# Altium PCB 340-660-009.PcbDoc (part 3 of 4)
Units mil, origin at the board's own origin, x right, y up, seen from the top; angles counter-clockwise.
Board outline 2755.91 x 2755.91 mil, 4 copper layers (Top Layer, Int1 (PWR), Int2 (GND), Bottom Layer), stack 53.912 mil thick; 183 components, 253 nets, 930 pads, 492 vias.
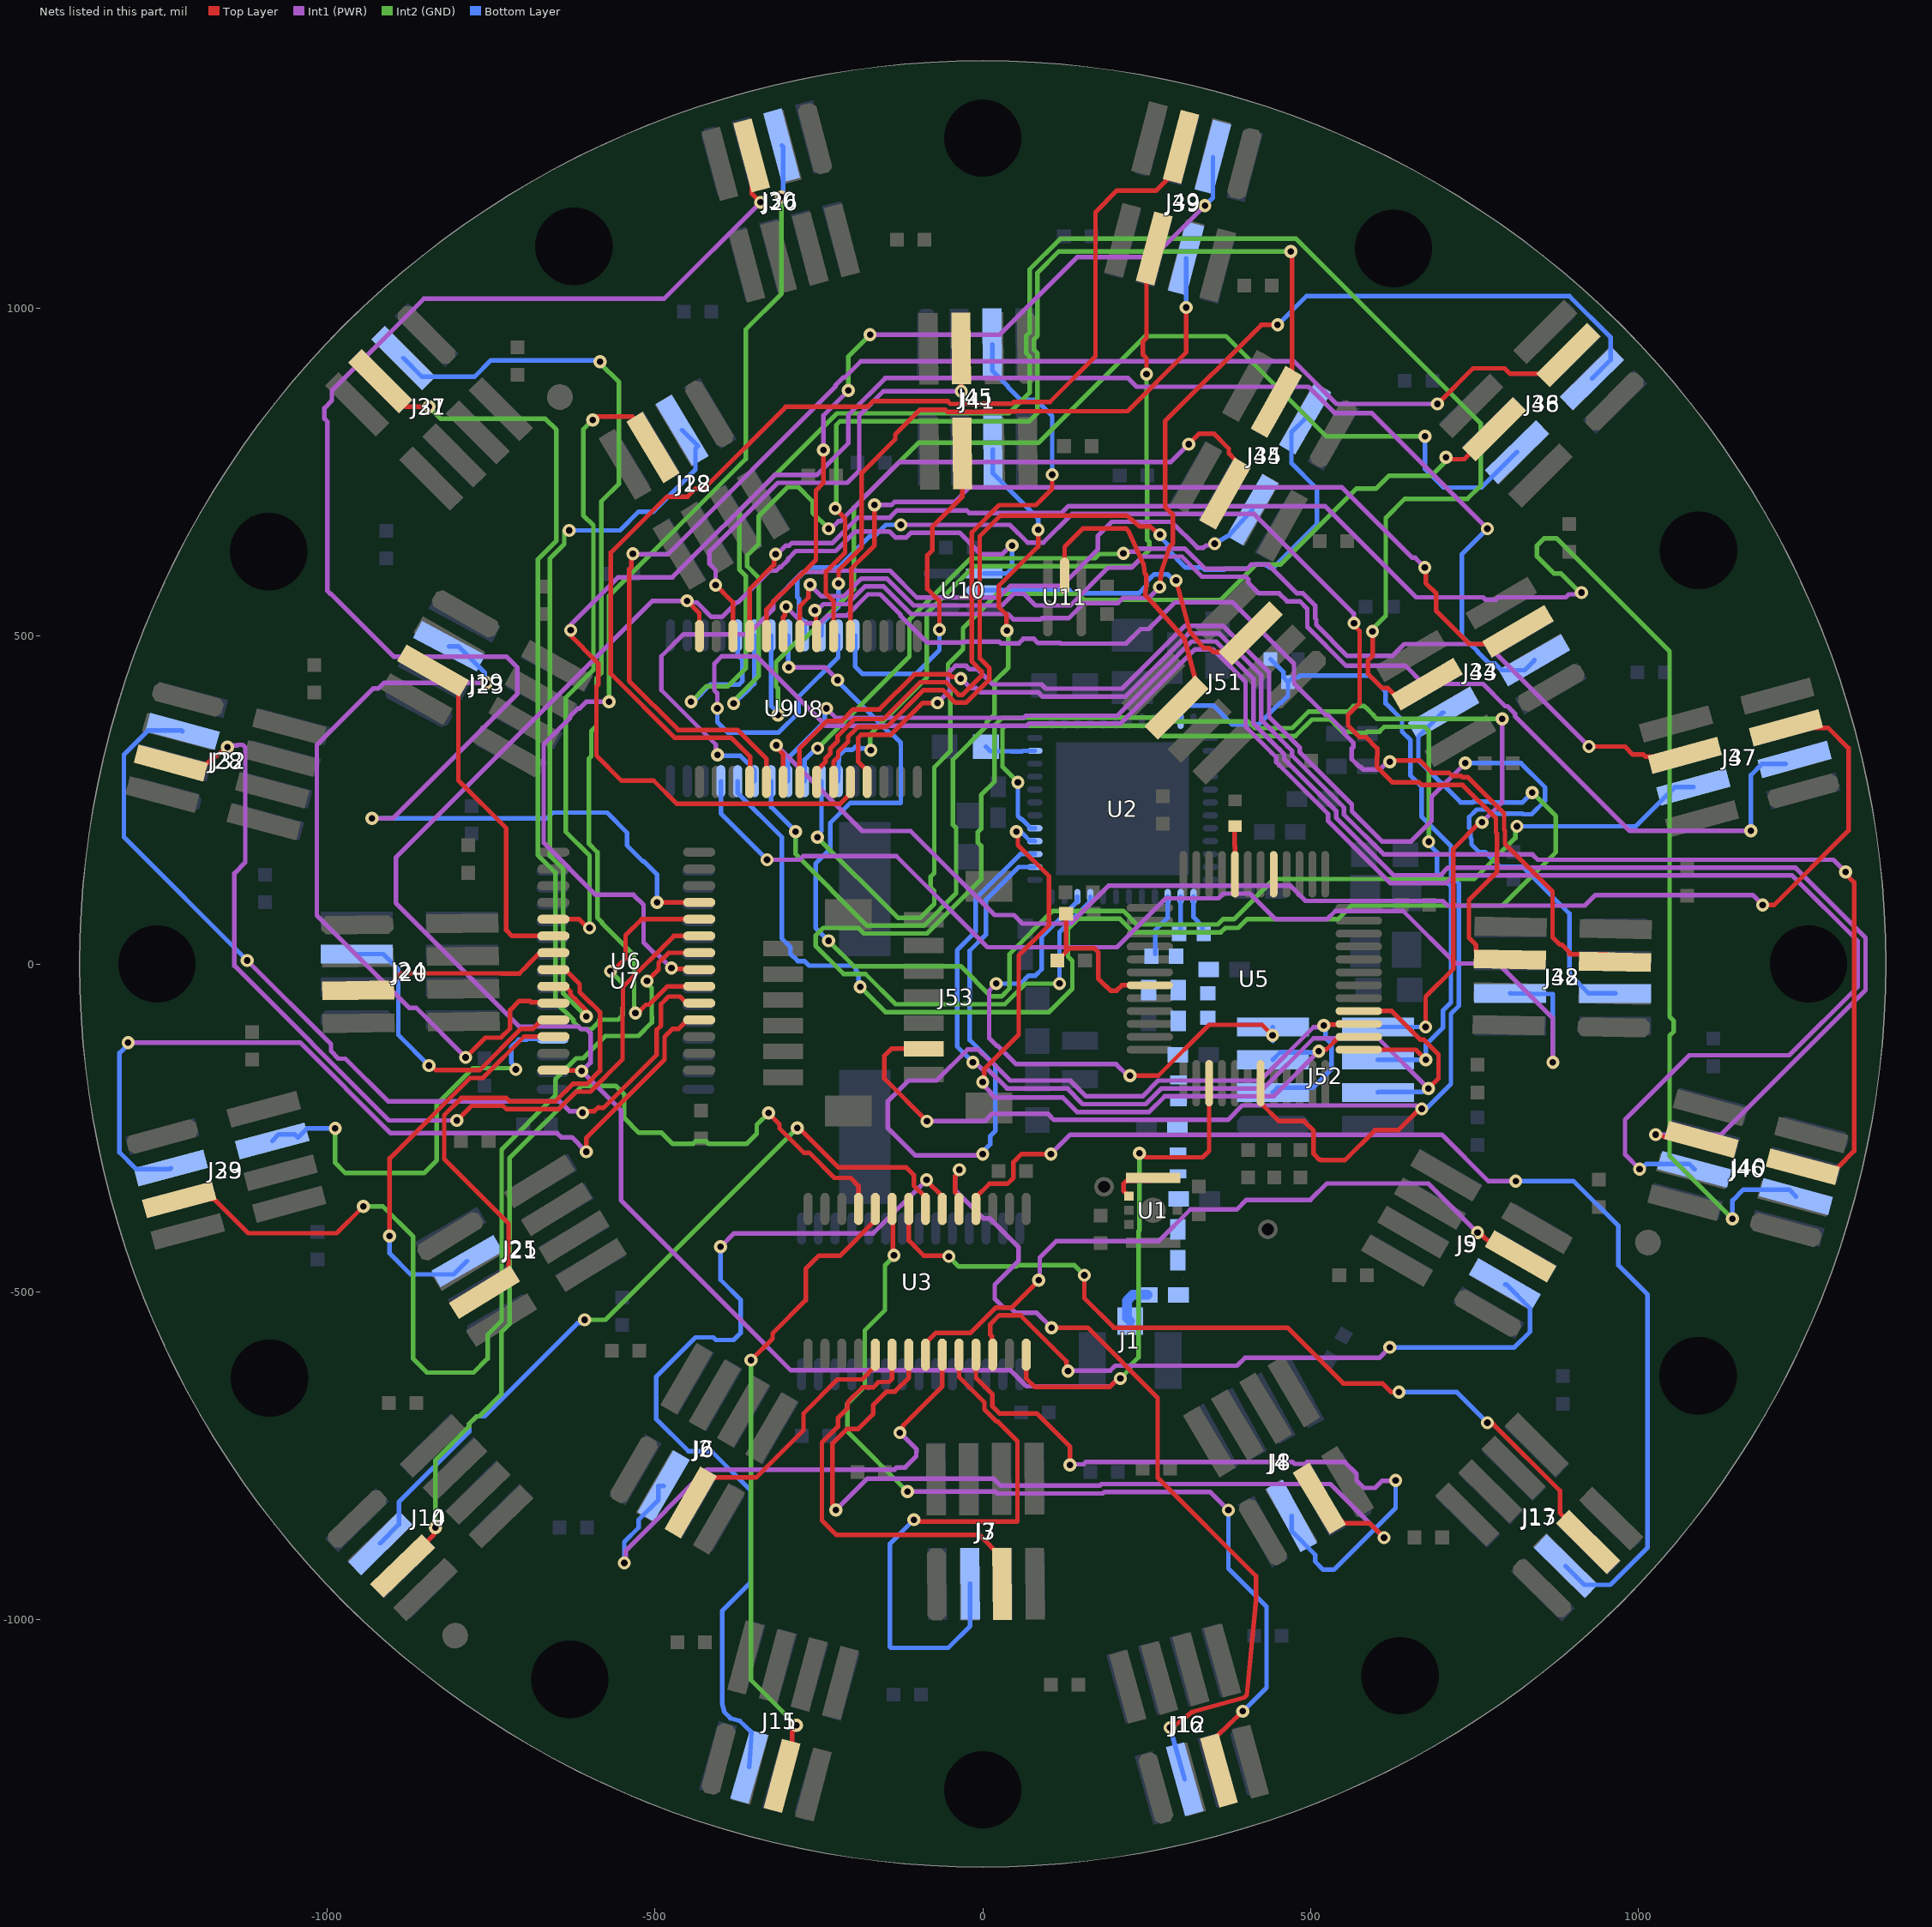
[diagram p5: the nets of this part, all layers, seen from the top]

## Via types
v1: diameter 20, hole 10, Top Layer to Bottom Layer, tented both sides, 489 vias
v2: diameter 20, hole 10, Top Layer to Bottom Layer, 3 vias

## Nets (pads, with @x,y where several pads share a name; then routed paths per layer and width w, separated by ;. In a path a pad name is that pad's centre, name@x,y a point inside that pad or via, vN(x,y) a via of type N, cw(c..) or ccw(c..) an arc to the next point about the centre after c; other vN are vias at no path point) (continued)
MUXA32: J33.6 U7.4 | length 665.4
  Int2 (GND) w7: v1(-988,-251) -988,-303.5 -972.5,-319 -852.37,-319 -833,-299.63 -833,-214.08 -777.92,-159 -714.4,-159 v1(-712.37,-161.02)
  Bottom Layer w7: J33.6@-1084.08,-270.12 -1073.97,-260 -1050,-260 -1045,-265 -1031,-251 v1(-988,-251) ; v1(-712.37,-161.02) -712.37,-157.51 -719.5,-150.38 -719.5,-126.92 -708.08,-115.5 -695.93,-115.5 -695,-114.57 U7.4@-656.22,-114.57
MUXA33: J34.6 U9.19 | length 2667.8
  Top Layer w7: v1(594.61,507.18) 595.2,506.59 595.2,470.1 587.99,462.88 587.99,442.48 609.57,420.9 618.3,420.9 628.2,411 662.8,411 J34.6@678.39,426.59
  Int2 (GND) w7: v1(-445,400) -421.33,423.67 -388.75,423.67 -361.56,450.86 -361.56,592.01 -371.5,601.95 -371.5,690.97 -222.47,840 40,840 71.57,871.57 71.57,926.68 66.27,931.98 66.27,958.07 71.57,963.38 71.57,1059.54 118.53,1106.5 478.08,1106.5 760,824.58 760,730 739.5,709.5 643.92,709.5 615,680.58 615,531.09 594.61,510.7 v1(594.61,507.18)
  Bottom Layer w7: v1(-445,400) -441.5,400 -415.19,426.31 -371.66,426.31 -366.46,431.51 -366.46,463.49 -373.98,471 U9.19@-373.98,501.22
MUXA34: J35.6 U9.20 | length 1354.8
  Top Layer w7: v1(314.2,793) 330.2,809 352.5,809 375.48,786.02 375.48,778.96 385.37,769.06 385.37,733.02 J35.6@369.86,717.51
  Int1 (PWR) w7: v1(-235.05,664.05) -231.53,664.05 -220.08,675.5 -216.92,675.5 -184.6,707.82 -184.6,708.36 -126.97,765.99 287.19,765.99 v1(314.2,793)
  Int2 (GND) w7: v1(-380.1,397.47) -380.1,400.9 -342,439 -342,589.42 -359.5,606.92 -359.5,623.08 -342,640.58 -342,683.08 -297.58,727.5 -281.42,727.5 -259.48,705.56 -259.48,688.48 v1(-235.05,664.05)
  Bottom Layer w7: v1(-380.1,397.47) -379.21,397.47 -362.68,414 -361.89,414 -348.39,427.5 U9.20@-348.39,501.22
MUXA35: J36.6 U9.21 | length 1765.2
  Int2 (GND) w7: v1(-312.53,379.69) -312.53,420.5 -315.4,423.37 -315.4,460.66 -280.02,496.03 -271.98,496.03 -196.5,571.52 -196.5,696.47 -97.97,795 85,795 247.85,957.85 371.23,957.85 524.07,805 v1(675,805)
  Bottom Layer w7: U9.21@-322.8,501.22 -322.8,393.47 -312.53,383.21 v1(-312.53,379.69) ; v1(675,805) 675,755 703.15,726.85 761.03,726.85 J36.6@815.26,781.08
MUXA36: J37.6 U9.22 | length 2229.8
  Int1 (PWR) w7: v1(-295.9,452.58) -240.84,452.58 v1(-221.33,433.08)
  Int2 (GND) w7: v1(-235.37,35.38) -196.58,-3.41 -33.55,-3.41 12.54,-49.5 28.69,-49.5 40.85,-37.34 40.85,15 106.81,80.96 214.36,80.96 235.14,60.18 358.25,60.18 366.27,68.2 383.1,68.2 444.39,129.5 750.08,129.5 812.72,192.14 812.72,207.49 v1(815.21,209.98)
  Bottom Layer w7: U9.22@-297.2,501.22 -296.55,500.57 -296.55,453.24 v1(-295.9,452.58) ; v1(-235.37,35.38) -254.87,54.88 -254.87,153.08 -232.77,175.17 -232.77,214.96 -202.06,245.67 -125,245.67 -125,335 -125.5,335.5 -125.5,338.08 -136.92,349.5 -139.5,349.5 -225,435 -223.25,435 v1(-221.33,433.08) ; v1(815.21,209.98) 996.5,210 1056.16,269.66 J37.6@1084.37,269.66
MUXA37: J38.6 U9.23 | length 1832.4
  Top Layer w7: v1(566.5,520) 566.5,516.48 575,507.98 575,398.03 557.31,380.34 557.31,363.57 574.82,346.06 584.66,346.06 602.16,328.55 602.16,316.97 601.77,316.58 601.77,300.42 625.19,277 665.94,277 669.94,273 732.32,273 783.03,222.29 783.03,200.2 784.88,198.35 784.88,140.5 741.98,97.6 741.98,39.76 752.89,28.85 752.89,18.92 765.15,6.66 J38.6@804.62,6.66
  Int1 (PWR) w7: v1(-125,670) 41.33,670 68.33,643 92.58,643 136.08,686.5 414.32,686.5 566.16,534.65 566.16,520.34 v1(566.5,520)
  Bottom Layer w7: U9.23@-271.61,501.22 -271.61,520.77 -280.5,529.66 -280.5,556.87 -282.99,559.35 -282.99,586.56 -264.55,605 -219.71,605 -172.07,652.64 -164.98,652.64 -147.62,670 v1(-125,670)
MUXA38: J39.6 U9.24 | length 995.1
  Top Layer w7: v1(-220,580.39) -219.82,580.58 -219.82,600.89 -184.6,636.11 -184.6,749.32 -133.5,800.42 -133.5,808.02 -96.15,845.37 -57.34,845.37 -54.35,842.38 -0.06,842.38 0.4,842.84 49.94,842.84 50.39,843.29 220.87,843.29 310.47,932.89 v1(310.47,1001.57)
  Bottom Layer w7: U9.24@-246.02,501.22 -246.02,518.94 -220,544.96 v1(-220,580.39) ; v1(310.47,1001.57) J39.6@310.47,1076.4
MUXA39: J40.6 U9.25 | length 3146.6
  Int1 (PWR) w7: v1(-405,390) -405,413.05 -409.5,417.55 -409.5,458.08 -398.08,469.5 -345.58,469.5 -239.64,363.57 67.57,363.57 70.82,366.82 210.65,366.82 323.83,480 351.21,480 401,430.21 401,362.07 440.82,322.24 448,315.07 448,307.82 527.2,228.61 527.2,218.01 621.71,123.5 708.05,123.5 719.55,135 1235,135 1335,35 1335,-35 1230.59,-139.41 1078.02,-139.41 980,-237.42 980,-290.65 v1(1002.35,-313)
  Bottom Layer w7: v1(-405,390) -405,369 -389.15,353.15 -311.5,353.15 -281,383.65 -281,407.43 -220.43,468 U9.25@-220.43,501.22 ; v1(1002.35,-313) 1004.95,-313 1012.95,-305 1077.79,-305 J40.6@1086.14,-313.35
MUXA40: J41.6 U9.26 | length 525.6
  Top Layer w7: v1(-66,510) -66,553.65 -84.5,572.15 -84.5,623.35 -76.79,631.06 -76.79,667.21 -31.28,712.72 J41.6@-31.28,778.83
  Bottom Layer w7: U9.26@-194.84,501.22 -194.84,453.94 -183.42,442.52 -102.32,442.52 -66,478.84 v1(-66,510)
MUXA41: J42.6 U9.11 | length 1767.1
  Int1 (PWR) w7: v1(-329,159) -279.14,159 -273.64,164.5 -131.82,164.5 7.18,25.5 204.93,25.5 279.43,100 359.74,100 366.94,107.2 407.8,107.2 446.8,68.2 525.48,68.2 538.11,80.84 641.49,80.84 721.7,0.62 786.38,0.62 870,-83 v1(870,-150)
  Bottom Layer w7: U9.11@-399.57,278.78 -399.57,229.57 v1(-329,159) ; J42.6@804.88,-45 870,-46 v1(870,-150)
MUXA42: J43.6 U9.10 | length 2097.7
  Int2 (GND) w7: v1(-187,-34.91) -148.41,-73.5 101.25,-73.5 136.67,-38.08 136.67,4.49 130.14,11.01 130.14,53.58 145.53,68.96 209.39,68.96 223.35,55 230.17,48.18 363.22,48.18 370.04,55 390,55 403.2,68.2 541.99,68.2 562.78,88.99 793.07,88.99 874.5,170.42 874.5,225.53 v1(838.56,261.48)
  Bottom Layer w7: U9.10@-373.98,278.78 -373.98,261.06 -306.5,193.59 -306.5,38.92 -293.56,25.98 -293.56,15.74 -282.13,4.32 -271.9,4.32 -264.96,-2.61 -198.1,-2.61 -193.15,-7.56 -193.15,-10.7 -189.44,-14.41 -189.44,-32.47 v1(-187,-34.91) ; J43.6@703.12,383.29 701.35,383.29 664.77,346.71 664.77,310.96 729.23,246.5 747.67,246.5 748.68,247.51 774.78,247.51 775.79,246.5 823.58,246.5 v1(838.56,261.48)
MUXA43: J44.6 U9.9 | length 1348.7
  Int1 (PWR) w7: v1(-404.75,318.79) -407.24,321.28 -407.24,334.66 -490.31,417.73 -490.31,469.37 -456.73,502.95 -358.05,502.95 -319.5,541.5 -319.5,553.08 -274.59,597.99 -244.51,597.99 -242.61,599.89 -141.4,599.89 -100.51,559 24.45,559 41.95,576.5 120.08,576.5 175.5,631.92 175.5,653.08 196.92,674.5 288.08,674.5 327.58,635 337,635 340.57,638.57 351.51,638.57 v1(354,641.06)
  Bottom Layer w7: v1(-404.75,318.79) -403.47,317.51 -369.9,317.51 -348.39,296 U9.9@-348.39,278.78 ; v1(354,641.06) 376.3,654.12 J44.6@411.59,693.12
MUXA44: J45.6 U9.8 | length 1210.8
  Top Layer w7: v1(37.05,508.68) 36.32,509.42 36.32,532.68 24.5,544.5 24.5,576.92 84.5,636.92 v1(84.5,662.5)
  Int2 (GND) w7: v1(-285.5,202) -285.5,167.55 -176.45,58.5 -89.88,58.5 -40.5,107.88 -40.5,207.42 -45.26,212.18 -45.26,311.71 6,362.97 6,368.84 18,380.84 18,431.23 39,452.23 39,506.74 v1(37.05,508.68)
  Bottom Layer w7: U9.8@-322.8,278.78 -322.8,239.3 v1(-285.5,202) ; J45.6@15.5,785.04 15.5,748.5 84.5,679.5 v1(84.5,662.5)
MUXA45: J46.6 U9.7 | length 2584.1
  Top Layer w7: v1(1026.93,-260.41) 1044.12,-265.03 J46.6@1096.59,-267.89
  Int1 (PWR) w7: v1(-238.5,390) -224.07,375.57 62.6,375.57 65.85,378.82 205.68,378.82 318.86,492 356.18,492 413,435.18 413,367.04 452.82,327.21 460,320.04 460,312.79 539.2,233.58 539.2,222.98 626.68,135.5 698.58,135.5 710,146.92 714.5,146.92 714.58,147 1226.92,147 1239.97,147 1347,39.97 1347,26.92 1347,-39.97 1340.56,-46.42 1126.56,-260.41 v1(1026.93,-260.41)
  Bottom Layer w7: U9.7@-297.2,278.78 -297.2,313.89 -240.99,370.1 -240.99,387.51 v1(-238.5,390)
MUXA46: J47.6 U9.6 | length 1710.5
  Top Layer w7: v1(925.06,331.61) 979.81,331.61 991.92,319.5 1008.08,319.5 1011.36,316.21 1069.29,316.21 J47.6@1071.13,318.05
  Int1 (PWR) w7: v1(214.5,626.52) 216.99,629.01 234.46,629.01 239.01,633.56 308.88,633.56 339.6,602.84 403.31,602.84 409.74,609.26 435.89,609.26 479.8,565.36 488.74,565.36 507.19,546.91 507.19,527.47 509,525.66 509,517.3 556.3,470 624.98,470 643.01,488.03 768.65,488.03 v1(925.06,331.61)
  Int2 (GND) w7: v1(-251.89,329.11) -111.78,469.22 -111.78,525.19 -18.05,618.92 171.5,618.92 178.08,625.5 213.48,625.5 v1(214.5,626.52)
  Bottom Layer w7: U9.6@-271.61,278.78 -271.61,311.61 -254.11,329.11 v1(-251.89,329.11)
MUXA47: J48.6 U9.5 | length 1724.7
  Top Layer w7: v1(706.89,773.11) 710,770 734.66,770 J48.6@780.33,815.67
  Int2 (GND) w7: v1(-252.27,193.27) -129.5,70.5 -115.09,70.5 -94.85,70.5 -74,91.35 -74,111.42 -79.5,116.92 -79.5,133.08 -74,138.58 -74,299.94 -49.5,324.44 -49.5,423.89 -52.97,427.36 -52.97,457.03 -30,480 -30,512.25 22.25,564.5 145.67,564.5 154.67,555.5 362.92,555.5 416.69,609.26 454.26,609.26 570,725 600,725 620,745 685,745 710,770 v1(706.89,773.11)
  Bottom Layer w7: v1(-252.27,193.27) -252.27,196.79 -246.02,203.04 U9.5@-246.02,278.78
MUXA48: J49.6 U9.4 | length 1191.3
  Top Layer w7: v1(250,900) 250,923.9 244.46,929.43 244.46,949.81 250,955.35 250,1079.83 J49.6@261.82,1091.65
  Int2 (GND) w7: v1(-170.72,326.17) -171.76,327.21 -171.76,350.24 -85.5,436.5 -85.5,534.5 -13.08,606.92 229.35,606.92 254.35,631.92 254.35,643.58 251,646.92 251,760.45 250,761.45 v1(250,900)
  Bottom Layer w7: U9.4@-220.43,278.78 -219.43,318 -210.82,326.61 -198.9,326.61 -194.24,331.28 -188.44,331.28 -185.82,328.66 -173.2,328.66 v1(-170.72,326.17)
MUXA49: J51.6 U11.2 | length 464
  Top Layer w7: U11.2@125,592.29 125,636.58 152.92,664.5 217.12,664.5 218.43,664.5 222.53,660.4 245.73,608.23 247.31,595.27 249.5,593.08 249.5,576.92 248.38,567.53 248.38,561.73 259.35,550.76 307.87,496.25 324.2,435.21 J51.6@295.67,391.03
MUXB1: J2.5 U3.19 | length 401.4
  Top Layer w7: J2.5@-445.67,-821.73 -445.67,-820.08 -409.04,-783.45 -345.52,-783.45 -273.49,-711.43 -273.49,-685.92 -221.58,-634 -184.04,-634 -163.98,-613.94 U3.19@-163.98,-596.22
MUXB2: J3.5 U3.20 | length 654.3
  Top Layer w7: U3.20@-138.39,-596.22 -138.39,-633.24 -142.28,-637.13 -159.39,-638.39 -167,-646 -183.46,-646 -205.5,-668.04 -205.5,-669.84 -206.35,-670.69 -206.35,-677.92 -221,-692.57 -221,-706.03 -245.35,-730.38 -245.35,-849.15 -223.5,-871 -5.38,-871 29.62,-906 J3.5@29.62,-946.12
MUXB3: J4.5 U3.21 | length 1323.6
  Top Layer w7: v1(-224,-833) -224,-829.48 -229.5,-823.98 -229.5,-731.92 -206.96,-709.38 -189.89,-709.38 -167.35,-686.84 -167.35,-673.42 -146.3,-652.37 -133.84,-652.37 -112.8,-631.33 U3.21@-112.8,-596.22 ; J4.5@513.61,-815.67 513.61,-816.17 550.7,-853.26 590.26,-853.26 v1(612.29,-875.29)
  Int1 (PWR) w7: v1(-224,-833) -176.5,-785.5 16.98,-785.5 27.48,-796 178.49,-796 180.99,-793.5 530.5,-793.5 v1(612.29,-875.29)
MUXB4: J5.5 U3.22 | length 1054.8
  Top Layer w7: U3.22@-87.2,-596.22 -87.2,-578.5 -71.81,-563.11 -18.82,-563.11 20.15,-524.14 44.38,-524.14 85.27,-483.25 v1(85.27,-482.45) ; v1(755,-410) 758.52,-410 778.52,-430 J5.5@790,-430
  Int1 (PWR) w7: v1(85.27,-482.45) 86.97,-480.75 86.97,-448.03 111.97,-423.03 268.48,-423.03 317.01,-374.5 387.76,-374.5 402.26,-360 500,-360 525,-335 680,-335 v1(755,-410)
MUXB5: J6.5 U3.23 | length 862
  Top Layer w7: v1(-126.38,-715.17) -126.38,-711.65 -121.96,-707.24 -121.96,-704.59 -61.61,-644.25 U3.23@-61.61,-596.22
  Int1 (PWR) w7: v1(-547,-914) -544.51,-911.51 -544.51,-894.96 -421.05,-771.5 -134.54,-771.5 -131.26,-768.22 -118.22,-768.22 -101.32,-751.32 -101,-740.5 v1@-126.33,-715.17
  Bottom Layer w7: v1(-547,-914) -547,-882 -525,-860 -525,-847.98 -494.69,-817.68 -494.69,-796.69 J6.5@-486.88,-796.69
MUXB6: J7.5 U3.24 | length 861.8
  Top Layer w7: v1(-105,-848) -102,-851 52,-851 53,-850 53,-727.94 23.15,-698.08 21.02,-698.08 2.56,-679.63 2.56,-668.91 -36.02,-630.32 U3.24@-36.02,-596.22
  Bottom Layer w7: v1(-105,-848) -141.5,-884.5 -141.5,-1042 -140,-1043.5 -52.66,-1043.5 -19.16,-1010 J7.5@-19.16,-945.76
MUXB7: J8.5 U3.25 | length 1082.6
  Top Layer w7: U3.25@-10.43,-596.22 -10.43,-631.33 14.56,-656.32 14.56,-674.66 25.99,-686.08 83.08,-686.08 133,-736 v1(133,-764.5)
  Int1 (PWR) w7: v1(133,-764.5) 134,-763.5 153.5,-763.5 157,-760 473.08,-760 475.91,-762.83 492.06,-762.83 494.9,-760 552.45,-760 570.5,-778.05 570.5,-788.08 581.92,-799.5 598.45,-799.5 609.5,-788.45 629.55,-788.45 v1(630,-788)
  Bottom Layer w7: J8.5@471.44,-842.3 471.44,-865.61 507.37,-901.54 507.37,-911.98 519.62,-924.23 535.77,-924.23 630,-830 v1(630,-788)
MUXB8: J9.5 U3.26 | length 1033.8
  Top Layer w7: U3.26@15.16,-596.22 13.86,-594.92 13.86,-568.11 11.58,-565.83 11.58,-549.68 25.12,-536.14 57.74,-536.14 127.77,-606.18 127.77,-618.69 v1(130.26,-621.17)
  Int1 (PWR) w7: v1(130.26,-621.17) 130.94,-620.5 194.42,-620.5 201.92,-613 388.05,-613 400.05,-601 605,-601 v1(621,-585)
  Bottom Layer w7: v1(621,-585) 811.31,-585 835.1,-561.21 835.1,-525.45 798.53,-488.88 J9.5@796.76,-488.88
MUXB9: J10.5 U3.11 | length 1443.8
  Top Layer w7: J10.5@-885.18,-918.69 -837.49,-871 -837.49,-862.49 v1(-835,-860) ; v1(-326.65,-227.35) -326.65,-228.02 -310.01,-244.65 -310.01,-250.86 -272.72,-288.15 -264.57,-288.15 -226.22,-326.5 -201.74,-326.5 -189.57,-338.67 U3.11@-189.57,-373.78
  Int2 (GND) w7: v1(-835,-860) -835,-757 -783.44,-705.44 -783.44,-701.55 -772.02,-690.13 -768.13,-690.13 -734.5,-656.5 -734.5,-561.92 -722,-549.42 -722,-296.58 -611.42,-186 -560,-186 -547,-199 -547,-235 -524.5,-257.5 -490.08,-257.5 -473.08,-274.5 -442.08,-274.5 -438.08,-270.5 -421.92,-270.5 -417.92,-274.5 -360.5,-274.5 -344.82,-258.82 -344.82,-245.52 v1(-326.65,-227.35)
MUXB10: J11.5 U3.10 | length 1000.6
  Top Layer w7: v1(-353.59,-604.58) -320.63,-571.62 -320.63,-563.66 -270.07,-513.1 -270.07,-465.07 -250,-445 -217.48,-445 -163.98,-391.5 U3.10@-163.98,-373.78 ; J11.5@-306.44,-1238.85 -290.62,-1223.03 -290.62,-1171.53 -284.27,-1165.19 v1(-284.27,-1161.67)
  Int2 (GND) w7: v1(-353.59,-604.58) -353.59,-1092.35 v1(-284.27,-1161.67)
MUXB11: J12.5 U3.9 | length 1456.4
  Top Layer w7: U3.9@-138.39,-373.78 -137.09,-375.08 -137.09,-442.87 v1(-135.43,-444.54) ; J12.5@360.5,-1230.52 357.42,-1178.01 375.54,-1160.54 v1(396.89,-1140.2)
  Int1 (PWR) w7: v1(-115,-805) 19.51,-805 22.51,-808 183.46,-808 185.96,-805.5 346.9,-805.5 v1(374.79,-833.39)
  Int2 (GND) w7: v1(-135.43,-444.54) -135.43,-446.11 -149.13,-459.82 -149.13,-528.3 -179.89,-559.05 -179.89,-644.23 -206.35,-670.69 -206.35,-713.65 v1(-115,-805)
  Bottom Layer w7: v1(374.79,-833.39) 374.79,-922.21 433,-980.42 433,-1104.08 v1(396.89,-1140.2)
MUXB12: J13.5 U3.8 | length 1317.8
  Top Layer w7: U3.8@-112.8,-373.78 -112.8,-422.2 -90,-445 -52.98,-445 v1(-51.67,-446.31) ; v1(155,-475) 155,-510 200,-555 465,-555 550,-640 610,-640 623.39,-653.39 v1(635.15,-653.39) ; v1(770,-700) 772.49,-702.49 779.46,-702.49 880.88,-803.91 880.88,-837.79 923.67,-880.58 J13.5@923.67,-881.78
  Int2 (GND) w7: v1(-51.67,-446.31) -36.38,-461.61 50.78,-461.61 52.62,-459.77 139.77,-459.77 v1(155,-475)
  Bottom Layer w7: v1(635.15,-653.39) 723.39,-653.39 v1(770,-700)
MUXB13: J14.5 U3.7 | length 1192.8
  Top Layer w7: v1(-283,-250.3) -280.23,-250.3 -220.03,-310.5 -116.55,-310.5 -105.13,-321.92 -105.13,-338.14 -87.2,-356.06 U3.7@-87.2,-373.78
  Int2 (GND) w7: v1(-607.5,-543) -575.7,-543 v1(-283,-250.3)
  Bottom Layer w7: J14.5@-919.41,-883.81 -890.94,-855.34 -890.94,-820.99 -783.44,-713.49 -783.44,-701.55 -772.02,-690.13 -760.08,-690.13 -617.72,-547.77 -615.79,-547.77 -611.02,-543 v1(-607.5,-543)
MUXB14: J15.5 U3.6 | length 1431
  Top Layer w7: v1(-85.63,-329.5) -85.63,-330.77 -61.61,-354.79 U3.6@-61.61,-373.78
  Int1 (PWR) w7: v1(-400.03,-431.55) -379.48,-411 -167.13,-411 v1(-85.63,-329.5)
  Bottom Layer w7: v1(-400.03,-431.55) -400.03,-481.81 -369.5,-512.34 -369.5,-563.18 -380,-573.68 -407.06,-573.68 -411.01,-569.74 -438.07,-569.74 -498.27,-629.93 -498.27,-694.31 -449.08,-743.5 -413.81,-743.5 -354.41,-802.9 -354.41,-943.78 -397.67,-987.05 -397.67,-1125.03 -397.67,-1127.93 -394.2,-1141.63 -384.92,-1150.91 -370.58,-1155.02 -352.57,-1172.66 J15.5@-356.09,-1225.14
MUXB15: J16.5 U3.5 | length 1364.7
  Top Layer w7: U3.5@-36.02,-373.78 -36.02,-354.23 -42.24,-348.01 -42.24,-324.37 -35.5,-317.63 v1(-35.5,-314.11) ; v1(105,-555) 160.08,-555 267,-661.92 267,-784.02 417.07,-934.09 417.07,-970.3 403.08,-1115.3 399,-1119.38 320.69,-1141.09 319.34,-1141.47 289.07,-1165.21 286.65,-1165.21 286.23,-1165.21 v1(285.89,-1165.17)
  Int1 (PWR) w7: v1(-35.5,-314.11) -35.5,-317.63 -42.24,-324.37 -42.24,-344.84 1.3,-388.38 10.96,-388.38 54.5,-431.92 54.5,-453.47 18.39,-489.58 18.39,-511.13 31.41,-524.14 42.02,-524.14 49.88,-532 82,-532 v1(105,-555)
  Bottom Layer w7: v1(285.89,-1165.17) 294,-1194.44 J16.5@308.13,-1243.88
MUXB16: J17.5 U3.4 | length 1778.7
  Top Layer w7: U3.4@-10.43,-373.78 -10.43,-356.06 10.36,-335.27 38.02,-335.27 47,-326.29 47,-302.25 59.25,-290 v1(103.93,-290)
  Int1 (PWR) w7: v1(103.93,-290) 133.43,-260.5 700.5,-260.5 771.39,-331.39 v1(813.3,-331.39)
  Bottom Layer w7: v1(813.3,-331.39) 901.39,-331.39 970,-400 970,-460 1014.57,-504.57 1014.57,-890.43 957.72,-947.28 917.9,-947.28 J17.5@889.61,-918.99
MUXB17: J18.5 U6.19 | length 973.7
  Top Layer w7: U6.19@-655,68.23 -615.76,68.23 -602.54,55 v1(-600,55) ; v1(-595,830) -592.52,830 -597.52,835 -535,835 J18.5@-520,820
  Int2 (GND) w7: v1(-600,55) -600,165.5 -636.21,201.71 -636.21,406.33 -594,448.54 -594,669.01 -609.5,684.51 -609.5,815.5 v1(-595,830)
MUXB18: J19.5 U6.20 | length 488.6
  Top Layer w7: J19.5@-810,430 -800.19,420.19 -800.19,280.26 -727,207.08 -727,51.42 -718.22,42.64 U6.20@-655,42.64
MUXB19: J20.5 U6.21 | length 322
  Top Layer w7: J20.5@-952.79,-40.45 -912.99,-40.45 -886.96,-14.42 -734.33,-14.42 -734.25,-14.5 -706.92,-14.5 -695.05,-2.63 -695.05,-2 -676,17.05 U6.21@-655,17.05
MUXB20: J21.5 U6.22 | length 790.8
  Top Layer w7: J21.5@-760.18,-500.77 -723.54,-464.13 -723.54,-395.96 -821.79,-297.71 -821.79,-230.64 -795.65,-204.5 -726.95,-204.5 -721.95,-209.5 -651.89,-209.5 -625.3,-182.92 -603.84,-182.92 -584,-163.08 -584,-73.79 -587.84,-69.95 -587.84,-69.59 -598.42,-59 -599.31,-59 -609.89,-48.42 -614.91,-43.36 -614.91,-30.91 -637.28,-8.54 U6.22@-655,-8.54
MUXB21: J22.5 U6.23 | length 1161.1
  Top Layer w7: U6.23@-655,-34.13 -636.67,-34.13 -629,-41.81 -629,-46.24 -621.89,-53.35 -621.89,-53.86 -605,-70.75 v1(-605,-80)
  Int2 (GND) w7: v1(-631,661.46) -638.5,661.46 -638.5,640.53 -660.21,618.82 -660.21,164.68 -640,144.47 -640,-45 v1(-605,-80)
  Bottom Layer w7: v1(-631,661.46) -553.54,661.46 -525,690 -502.64,690 -438.36,754.29 -438.36,786.3 -434.5,790.15 J22.5@-458.8,814.45
MUXB22: J23.5 U6.24 | length 1150.1
  Top Layer w7: v1(-789.04,-142.54) -759,-112.5 -735.19,-112.5 -721.13,-98.44 -721.13,-70.56 -707.08,-56.5 -690.92,-56.5 -689,-58.43 -656.3,-58.43 U6.24@-655,-59.72
  Int1 (PWR) w7: v1(-789.04,-142.54) -864.58,-67 -875.08,-67 -1016.07,73.99 -1016.07,334.27 -929.88,420.46 -921.92,420.46 -913.38,429 v1(-757,429)
  Bottom Layer w7: J23.5@-814.02,484.68 -800.11,484.68 -759.49,444.06 -759.49,431.49 v1(-757,429)
MUXB23: J24.5 U6.25 | length 463.9
  Top Layer w7: v1(-845,-155) -841.48,-155 -834.44,-162.04 -767.76,-162.04 -704.63,-98.91 -686.31,-98.91 -672.72,-85.31 U6.25@-655,-85.31
  Bottom Layer w7: J24.5@-955.12,15 -914.76,15 -891.7,-8.07 -891.7,-108.3 v1(-845,-155)
MUXB24: J25.5 U6.26 | length 611.5
  Top Layer w7: v1(-905,-415) -905,-296.88 -782.16,-174.04 -762.79,-174.04 -699.66,-110.91 U6.26@-655,-110.91
  Bottom Layer w7: v1(-905,-415) -905,-441.68 -873.09,-473.59 -807.06,-473.59 J25.5@-786.88,-453.41
MUXB25: J26.5 U6.11 | length 2437.8
  Top Layer w7: v1(-497,93.82) U6.11@-432.56,93.82 ; J26.5@-352.59,1233.43 -352.59,1175.59 v1(-339,1162)
  Int1 (PWR) w7: v1(-932,222) -900,222 -710,412 -710,452 -726.83,468.83 -898.83,468.83 -995,565 -995.9,565 -1000,569.1 -1000,827.42 -1004.5,831.92 -1004.5,848.08 -993.08,859.5 -993.08,874.5 -852.58,1015 -486,1015 v1(-339,1162)
  Bottom Layer w7: v1(-932,222) -664.91,222 -656.07,230.84 -573.27,230.84 -542.7,200.27 -542.7,180.73 -518.47,156.5 -516.95,156.5 -497,136.55 v1(-497,93.82)
MUXB26: J27.5 U6.10 | length 1591.9
  Top Layer w7: J27.5@-919.28,889.07 -880.21,850 v1(-845,850) ; v1(-568,-11) -564.5,-11 -545,8.5 -545,43.64 -520.41,68.23 U6.10@-432.56,68.23
  Int2 (GND) w7: v1(-845,850) -826.74,831.74 -667.24,831.74 -650.5,815 -650.5,645.5 -678.85,617.15 -678.85,166.35 -652,139.5 -652,-58 -625,-85 -624.5,-85 -624.5,-88.08 -613.08,-99.5 -596.92,-99.5 -585.5,-88.08 -585.5,-85 -556,-85 -549.5,-78.5 -549.5,-66.92 -548.84,-66.26 -548.84,-30.16 v1(-568,-11)
MUXB27: J28.5 U6.9 | length 1458
  Top Layer w7: J28.5@-1238.86,306.55 -1186.32,303.96 v1(-1152.38,330.64) ; v1(-802.29,-238.71) -780.08,-216.5 -731.92,-216.5 -726.92,-221.5 -646.92,-221.5 -620.33,-194.92 -598.87,-194.92 -549.5,-145.55 -549.5,-66.92 -548.84,-66.26 -548.84,-34.98 -471.21,42.64 U6.9@-432.56,42.64
  Int1 (PWR) w7: v1(-1152.38,330.64) -1149.89,333.12 -1137.51,333.12 -1136.32,334.32 -1129.32,334.32 -1125.22,330.22 -1125.22,154.78 -1141.79,138.21 -1141.79,-2.79 -905.86,-238.71 v1(-802.29,-238.71)
MUXB28: J29.5 U6.8 | length 1554.5
  Top Layer w7: J29.5@-1225.91,-359.89 -1224.65,-358.63 -1172.93,-358.63 -1120.66,-410.9 -985.9,-410.9 v1(-945,-370) ; v1(-512.3,-26.03) -494.5,-8.22 -494.5,1.7 -479.15,17.05 U6.8@-432.56,17.05
  Int2 (GND) w7: v1(-945,-370) -915.19,-370 -869,-416.19 -869,-602.58 -848.08,-623.5 -776.92,-623.5 -755.46,-602.04 -755.46,-565.91 -734,-544.45 -734,-283 -652,-201 -652,-175.92 -619.99,-143.92 -609.76,-143.92 -575.85,-110 -525.49,-110 -504.82,-89.33 -504.82,-80.18 -505,-80 -505,-36.72 -512.3,-29.41 v1(-512.3,-26.03)
MUXB29: J30.5 U6.7 | length 1589.5
  Top Layer w7: v1(-475,-6.37) -473.92,-7.46 -433.64,-7.46 U6.7@-432.56,-8.54
  Int1 (PWR) w7: v1(-570,400) -605,400 -615.5,389.5 -618.08,389.5 -629.5,378.08 -629.5,375.5 -670,335 -670,185 -590.5,105.5 -532.92,105.5 -517.46,90.03 -517.46,32.46 -499.28,14.28 -495.66,14.28 v1(-475,-6.37)
  Int2 (GND) w7: v1(-570,400) -570,561.97 -361.5,770.47 -361.5,968.08 -307,1022.58 v1(-307,1170)
  Bottom Layer w7: v1(-307,1170) -304.51,1172.49 -304.51,1246.78 J30.5@-306.59,1248.86
MUXB30: J31.5 U6.6 | length 1491.6
  Top Layer w7: v1(-530,-75) -526.74,-75 -513.87,-62.13 -508.92,-62.13 -480.92,-34.13 U6.6@-432.56,-34.13
  Int2 (GND) w7: v1(-584,918.7) -584,916.71 -555,887.71 -555,732.58 -582,705.58 -582,443.57 -589.5,436.07 -589.5,362.92 -597.21,355.21 -597.21,316.92 -600.84,313.29 -600.84,183.32 -588,170.47 -588,70.58 -580.5,63.08 -580.5,61.5 -531.8,12.8 -531.8,-73.2 v1(-530,-75)
  Bottom Layer w7: J31.5@-883.97,924.33 -855.44,895.8 -775.59,895.8 -750.39,921 -586.3,921 v1(-584,918.7)
MUXB31: J32.5 U6.5 | length 1409.5
  Top Layer w7: v1(-610.5,-227.02) -608.01,-224.53 -592.58,-224.53 -586.5,-218.45 -585.44,-219.51 -578.44,-219.51 -497.5,-138.58 -497.5,-100.53 -490.94,-93.97 -490.94,-61.13 -479.52,-49.7 -462.13,-49.7 -452.11,-59.72 U6.5@-432.56,-59.72
  Int1 (PWR) w7: v1(-1122.29,5.29) -994.5,-122.5 -994.5,-133.08 -983.08,-144.5 -972.5,-144.5 -907.5,-209.5 -645.5,-209.5 -630.47,-224.53 -612.99,-224.53 v1(-610.5,-227.02)
  Bottom Layer w7: J32.5@-1220.94,354.86 -1222.16,356.08 -1273.91,356.08 -1310.47,319.52 -1310.47,193.47 v1(-1122.29,5.29)
MUXB32: J33.5 U6.4 | length 1318.7
  Top Layer w7: v1(-605,-286.5) -605,-265.58 -485.5,-146.08 -485.5,-111.17 -473.22,-98.89 -463.85,-98.89 -450.28,-85.31 U6.4@-432.56,-85.31
  Int1 (PWR) w7: v1(-1304,-120) -1041.55,-120 -903.34,-258.21 -649.36,-258.21 -643.08,-264.5 -627,-264.5 v1(-605,-286.5)
  Bottom Layer w7: v1(-1304,-120) -1304,-122.75 -1317.12,-135.87 -1317.12,-287.56 -1291.84,-312.84 -1240.11,-312.84 J33.5@-1238.86,-311.59
MUXB33: J34.5 U8.19 | length 1300.7
  Top Layer w7: U8.19@-202.05,500 -202.05,558.69 -200.5,560.24 -200.5,603.24 -165.1,638.64 v1(-165.1,700.28) ; v1(674.5,605) 675.99,603.51 675.99,581 691.99,565 691.99,538.51 742.47,488.03 776.97,488.03 J34.5@780,485
  Int1 (PWR) w7: v1(-165.1,700.28) -139.26,700.28 -134.73,704.82 -42.75,704.82 -20.57,726.99 548.01,726.99 655.28,619.72 659.78,619.72 v1(674.5,605)
MUXB34: J35.5 U8.20 | length 1519
  Top Layer w7: U8.20@-227.64,500 -227.64,553.58 -239.5,565.45 -239.5,598.18 -210,627.68 -210,680 v1(-225,695) ; J35.5@448,857.4 467.68,892.63 472,892.63 472,1085 v1(470,1087)
  Int2 (GND) w7: v1(-225,695) -223.5,696.5 -223.5,822 -217.5,828 71.17,828 83.57,840.4 83.57,931.65 78.27,936.95 78.27,953.1 83.57,958.4 83.57,1054.57 116,1087 v1(470,1087)
MUXB35: J36.5 U8.21 | length 1745
  Top Layer w7: v1(-256.11,539.49) -254.53,537.9 -254.53,501.3 U8.21@-253.23,500 ; v1(270,575) 272.34,597.19 285.32,636.51 290,641.2 290,685.74 278.21,697.53 278.21,828.21 425,975 v1(450,975)
  Int1 (PWR) w7: v1(-256.11,539.49) -252.59,539.49 -243.18,548.89 -206.95,548.89 -179.95,575.89 -151.35,575.89 -109.29,533.84 38.58,533.84 46.92,525.5 88.08,525.5 90.2,527.61 131.36,527.61 154.24,550.5 206.25,550.5 214.01,558.26 253.26,558.26 v1(270,575)
  Bottom Layer w7: v1(450,975) 493.96,1018.96 895.23,1018.96 957.97,956.22 957.97,921.44 J36.5@929.73,893.2
MUXB36: J37.5 U8.22 | length 1940.8
  Top Layer w7: U8.22@-278.82,500 -278.82,546.18 -265.97,559.03 -265.97,576 v1(-263.49,578.49)
  Int1 (PWR) w7: v1(-263.49,578.49) -245.89,560.89 -211.92,560.89 -184.92,587.89 -146.38,587.89 -105.48,547 29.42,547 46.92,564.5 63.08,564.5 80.58,547 133.77,547 191.27,604.5 226.92,604.5 243.98,621.56 303.91,621.56 334.63,590.84 401.16,590.84 405.26,586.74 405.26,581.69 421.45,565.5 452.19,565.5 464.34,553.36 483.77,553.36 495.19,541.93 495.19,514.14 554.33,455 645,455 672.8,427.2 763.2,427.2 797.2,393.21 800.63,393.21 812.05,381.79 812.05,378.36 987.41,203 v1(1172,203)
  Bottom Layer w7: v1(1172,203) 1172,288 1189,305 J37.5@1225,305
MUXB37: J38.5 U8.23 | length 1751.1
  Top Layer w7: U8.23@-304.41,500 -304.41,529.29 -301.84,531.85 -301.84,543.16 v1(-300,545) ; v1(621.27,308.5) 623.27,310.5 666.39,310.5 685.41,291.48 711.75,291.48 716.32,286.91 730.06,286.91 731.97,285 740,285 795.5,229.5 795.5,204.7 796.88,203.32 796.88,183.12 869.43,110.57 869.43,40.57 880.62,29.38 883.7,29.38 895.12,17.95 895.12,14.88 895.21,14.79 953.19,14.79 J38.5@964.81,3.17
  Int1 (PWR) w7: v1(-300,545) -274.99,519.99 -248.03,519.99 -236.61,531.41 -207.47,531.41 -174.98,563.89 -156.32,563.89 -125.42,533 -125.42,531.05 -84.87,490.5 -30.54,490.5 -29.22,491.82 25.11,491.82 27.75,489.18 55.11,489.18 61.92,496 78.08,496 84.51,489.57 117.99,489.57 118.94,488.61 218.61,488.61 241.04,511.04 253.05,511.04 294.01,552 381.03,552 475,458.03 475,428.07 523.07,380 526.34,380 551.82,354.52 551.82,351.25 565.5,337.57 565.5,330.89 563.16,328.55 563.16,312.4 574.59,300.98 576.45,300.98 580.92,296.5 605.75,296.5 617.75,308.5 v1(621.27,308.5)
MUXB38: J39.5 U8.24 | length 1198.4
  Top Layer w7: U8.24@-330,500 -330,541 -319.5,551.5 -319.5,553.08 -308.08,564.5 -306.5,564.5 -254.55,616.45 -254.55,722.45 -243,734 v1(-243,784)
  Int1 (PWR) w7: v1(-243,784) -243,837 v1(-205,875) ; v1(-171.94,960) 25.73,960 144.42,1078.69 260.69,1078.69 v1(339,1157)
  Int2 (GND) w7: v1(-205,875) -205,926.94 v1(-171.94,960)
  Bottom Layer w7: v1(339,1157) 351.3,1169.3 J39.5@351.3,1231.34
MUXB39: J40.5 U8.25 | length 2901.5
  Top Layer w7: U8.25@-355.59,500 -355.59,571.83 -318.46,608.96 -318.46,622.45 v1(-315.98,624.94)
  Int1 (PWR) w7: v1(-315.98,624.94) -313.7,624.94 -300.34,638.3 -295.39,638.3 -291.69,642 -229.52,642 -190.73,680.78 -141.79,680.78 -130.58,692 -24.58,692 -20.57,687.99 120.6,687.99 131.11,698.5 522.21,698.5 661.42,559.29 763.31,559.29 766.68,555.92 782.84,555.92 786.21,559.29 889.73,559.29 894.46,564.01 911.25,564.01 v1(913.74,566.5)
  Int2 (GND) w7: v1(913.74,566.5) 911.53,566.5 882.57,595.46 871.97,595.46 845.5,621.92 845.5,638.08 856.92,649.5 875.5,649.5 1048.09,476.91 1048.09,-80.51 1054.5,-86.92 1054.5,-103.08 1048.09,-109.49 1048.09,-293.09 v1(1144,-389)
  Bottom Layer w7: v1(1144,-389) 1144,-361 1160.63,-344.37 1230.32,-344.37 J40.5@1240.88,-354.94
MUXB40: J41.5 U8.26 | length 744.5
  Top Layer w7: v1(-407.55,578.18) -381.18,551.81 U8.26@-381.18,500 ; v1(-32.75,873.88) J41.5@-32.75,939.05
  Int1 (PWR) w7: v1(-407.55,578.18) -407.55,600.87 -417,610.32 -417,629.5 -312.5,734 -207,734 -188.5,752.5 -188.5,837 -151.75,873.75 -32.87,873.75 v1(-32.75,873.88)
MUXB41: J42.5 U8.11 | length 2077.5
  Top Layer w7: U8.11@-176.46,277.56 -176.46,295.28 -190.22,309.04 -190.22,344.78 -185.5,349.5 -140.5,349.5 -91.68,398.32 v1(-69,398.32)
  Int1 (PWR) w7: v1(-69,398.32) -49.36,417.96 -49.36,423.75 -52.97,427.36 -52.97,443.52 -41.55,454.94 -25.39,454.94 -20.1,449.65 -8.07,449.65 15.01,426.57 89.49,426.57 96.12,419.94 212.86,419.94 308.92,516 366.12,516 437,445.12 437,376.98 476.82,337.16 484,329.98 484,322.73 563.2,243.53 563.2,232.92 609.13,186.99 653.45,186.99 685,218.54 685,255.17 v1(736.28,306.45)
  Bottom Layer w7: v1(736.28,306.45) 821.16,306.45 858.06,269.56 858.06,248.9 837.57,228.41 824.35,228.41 823.26,229.5 775.82,229.5 769.8,235.51 753.65,235.51 742.23,224.09 742.23,207.93 744.5,205.66 744.5,191.92 745.88,190.54 745.88,182.19 757.3,170.77 766.65,170.77 789.42,148 824.02,148 895.12,76.9 895.12,-0.04 895.46,-0.37 895.46,-15.69 924.76,-45 J42.5@965.12,-45
MUXB42: J43.5 U8.10 | length 2661.1
  Top Layer w7: v1(-628.71,509.11) -632.91,504.91 -586.66,458.66 -586.66,425.94 -589.5,423.1 -589.5,317.92 -551.26,279.69 -502.11,279.69 -466.87,244.45 -217.44,244.45 -202.05,259.84 U8.10@-202.05,277.56
  Int1 (PWR) w7: v1(-628.71,509.11) -632.91,513.31 -556.23,590 -473.47,590 -317.47,746 -253.42,746 -205.07,794.35 -205.07,837.4 -148.63,893.84 221.63,893.84 234.96,880.5 496.95,880.5 536.95,840.5 593.5,840.5 v1(770,664)
  Bottom Layer w7: v1(770,664) 731.2,625.2 731.2,500.01 743.19,488.03 744.1,488.03 755.52,476.6 755.52,475.7 773.08,458.13 781.76,458.13 791.66,448.23 826.71,448.23 J43.5@841.88,463.41
MUXB43: J44.5 U8.9 | length 1353.2
  Top Layer w7: U8.9@-227.64,277.56 -227.64,308.81 -220.39,316.07 -220.39,323.9 -205.43,338.86 -205.43,346.54 -190.47,361.5 -146.5,361.5 -90.18,417.82 -60.92,417.82 -41.75,398.65 -25.71,398.65 10.29,434.65 10.29,451.49 -4.5,466.28 -4.5,652.58 26.92,684 220,684 237.4,669.17 239.37,667.5 241.94,667.5 255.07,667.5 v1(270.5,655)
  Bottom Layer w7: v1(270.5,655) 270.5,651.48 281.81,640.17 281.81,632.37 309.41,604.77 335.44,604.77 338.71,601.5 368.29,601.5 369.51,602.72 403.31,602.84 416.69,609.26 429.99,609.26 437.77,604.77 443.57,604.77 510,671.2 510,725 471,764 471,811.17 J44.5@491.71,831.88
MUXB44: J45.5 U8.8 | length 1003.8
  Top Layer w7: U8.8@-253.23,277.56 -253.23,295.27 -239.64,308.86 -239.64,313.78 -232.39,321.04 -232.39,328.87 -221.26,340 -221.26,347.69 -195.44,373.5 -151.47,373.5 -95.15,429.82 -55.95,429.82 -36.78,410.65 -30.68,410.65 -1.71,439.62 -1.71,446.52 -16.5,461.31 -16.5,658.5 25,700 80.9,700 106,725.1 v1(106,746.49)
  Bottom Layer w7: J45.5@14.5,945.27 14.5,905.17 38.63,881.04 38.63,879.87 57.5,861 81,861 106,836 v1(106,746.49)
MUXB45: J46.5 U8.7 | length 2469.9
  Top Layer w7: U8.7@-278.82,277.56 -279.5,278.24 -279.5,329.08 -238.08,370.5 -215.41,370.5 -197.41,388.5 -157.5,388.5 -104.18,441.82 -50.98,441.82 -47.09,437.93 -35.96,437.93 v1(-33.47,435.44) ; J46.5@1251.34,-309.48 1252.64,-310.78 1304.33,-310.78 1329.63,-285.47 1329.63,124.54 1316.5,137.68 v1(1316.5,140.4)
  Int1 (PWR) w7: v1(-33.47,435.44) -32.99,435.44 -18.73,421.18 -10.3,421.18 -3.68,414.57 84.52,414.57 91.15,407.94 217.83,407.94 313.89,504 361.15,504 425,440.15 425,372.01 464.82,332.18 472,325.01 472,317.76 551.2,238.55 551.2,227.95 612.19,166.96 838.96,166.96 846.92,159 1297.9,159 v1(1316.5,140.4)
MUXB46: J47.5 U8.6 | length 2139.2
  Top Layer w7: v1(-314.85,333.65) -314.85,330.13 -304.41,319.69 U8.6@-304.41,277.56 ; v1(1190,90) 1207.6,90 1321,203.4 1321,329.19 1290,360.19 J47.5@1225.72,360.19
  Int1 (PWR) w7: v1(-314.85,333.65) -184.03,202.83 -110.25,202.83 18.08,74.5 47.53,74.5 60.49,61.55 133.97,61.55 191.63,119.2 469.52,119.2 492.48,96.25 702.01,96.25 709.27,88.99 918.81,88.99 934.89,105.07 1174.93,105.07 v1(1190,90)
MUXB47: J48.5 U8.5 | length 2105.8
  Top Layer w7: v1(-533.77,625.77) -536,623.55 -536,605.27 -539.5,601.77 -539.5,431.76 -464.72,356.98 -374.32,356.98 -330,312.67 U8.5@-330,277.56 ; v1(693.94,854.49) 748.11,908.66 796.42,908.66 804.63,900.45 865.08,900.45 J48.5@893.61,928.99
  Int1 (PWR) w7: v1(-533.77,625.77) -533,625 -480.52,625 -224.5,881.02 -224.5,883.08 -213.08,894.5 -211.02,894.5 -186.02,919.5 474.92,919.5 539.94,854.49 v1(693.94,854.49)
MUXB48: J49.5 U8.4 | length 1764.4
  Top Layer w7: U8.4@-355.59,277.56 -355.02,278.13 -355.02,316.54 -383.47,344.98 -469.69,344.98 -567.5,442.79 -567.5,627.5 -482.19,712.81 -450.57,712.81 -438.38,725 -425.53,725 -300.53,850 -176,850 -167.5,858.5 -53.5,858.5 -49.38,854.38 -5.03,854.38 -4.57,854.84 44.97,854.84 47.51,857.37 102.37,857.37 172,927 172,1147 205,1180 264.79,1180 302.65,1217.86 J49.5@302.65,1246.6
MUXB49: J51.5 U10.2 | length 513.1
  Top Layer w7: v1(295,585) 315.98,507.63 316.22,507.34 333.35,486.15 337.45,482.05 340.35,482.05 345.62,482.05 351.88,475.8 380.44,475.8 J51.5@408.97,504.33
  Bottom Layer w7: U10.2@2.29,570 132.34,570 136.84,565.5 238.08,565.5 250,577.42 250,582.58 261.92,594.5 281.98,594.5 291.48,585 v1(295,585)
NetC14_2: C14.2 L3.1 L6.1 U2.1 | length 56.7
  Bottom Layer w7: U2.1@321.63,102.68 321.63,71.27 335.1,57.8 L6.1@335.1,51.54
NetC15_1: C15.1 R3.1
NetC15_2: C15.2 C18.1 L5.2
NetC16_1: C16.1 C19.1 L3.2 L4.1
NetC17_1: C17.1 L4.2 L5.1
NetC19_2: C19.2 L6.2 L7.2 U2.2 | length 51.9
  Bottom Layer w7: L6.2@301.63,51.54 301.95,51.85 U2.2@301.95,97.68 ; U2.2@301.95,97.01 U2.2@301.95,97.68 ; U2.2@301.95,102.68 U2.2@301.95,97.68
NetC21_2: C21.2 U2.23 | length 78.2
  Bottom Layer w7: C21.2@4.86,331.54 11.83,324.57 43.06,324.57 43.62,324 59.78,324 60.89,325.12 U2.23@79.51,325.12
NetC22_1: C22.1 L7.1 U2.3 | length 95.8
  Bottom Layer w7: L7.1@263.37,15.27 263.37,51.54 282.26,70.43 U2.3@282.26,97.68 ; U2.3@282.26,97.07 U2.3@282.26,97.68 ; U2.3@282.26,102.68 U2.3@282.26,97.68
NetJ1_3: J1.3 R3.2 | length 68.3
  Bottom Layer w15: J1.3@225,-544.96 220,-539.96 220,-513.79 228.79,-505 R3.2@251.38,-505
NetR53_1: R53.1 U5.44 | length 73.8
  Top Layer w7: U5.44@384.86,136.8 384.86,179.84 384.55,180.15 384.55,209.86 R53.1@385,210.32
NetU1_1: U1.1 U1.7 | length 71.3
  Top Layer w7: U1.1@223.09,-354.13 219.7,-350.74 219.1,-350.74 215,-346.64 215,-335.05 219.1,-330.95 255.63,-330.95 U1.7@260,-326.57
NRESET: C20.2 J53.6 R57.1 U2.35 U5.19 | length 2487.5
  Top Layer w7: J53.6@-89.88,-129.44 -139.44,-129.44 -150,-140 -150,-175 v1(-85,-240) ; U5.19@424.23,-182.1 424.23,-212.31 451.92,-240 490.22,-240 504.79,-254.57 504.79,-289.79 513.79,-298.79 516.21,-298.79 516.92,-299.5 552.5,-299.5 598.39,-253.61 633.96,-253.61 666.44,-221.13 v1(669.96,-221.13)
  Int1 (PWR) w7: v1(-85,-240) 3.1,-240 14.64,-228.46 99.22,-228.46 108.64,-237.88 373.95,-237.88 395.91,-215.92 661.22,-215.92 666.44,-221.13 v1(669.96,-221.13)
  Bottom Layer w7: U2.35@301.95,370.39 301.95,390.12 306.05,394.22 351.91,394.22 380.88,365.25 420.66,365.25 454.19,398.79 455.62,398.79 465.83,409 465.83,429.83 R57.1@466,430 ; C20.2@439,465 459,445 459,437 R57.1@466,430 ; v1(669.96,-221.13) 672.44,-218.65 678.93,-218.65 714.5,-183.08 714.5,-75.91 726.5,-63.91 726.5,123.05 714.5,135.05 714.5,180.04 669.5,225.04 669.5,270.6 652.77,287.33 652.77,341.26 639.77,354.26 639.77,372.56 614.77,397.56 614.77,415.7 590.47,440 484.42,440 481.42,437 473,437 R57.1@466,430
NRST: C29.2 R52.1 U5.7 | length 267.4
  Top Layer w7: C29.2@114,5 127.27,18.27 ; R52.1@127.27,83.03 127.27,18.27 ; U5.7@254.94,-32.49 212.51,-32.49 204.24,-40.76 194.88,-40.76 188.32,-34.2 187.91,-34.2 176.49,-22.78 176.49,17.53 170.02,24 133,24 127.27,18.27
SCL: J52.8 U2.9 | length 2533.9
  Top Layer w7: v1(675.82,-96.13) 675.82,-49.89 717.98,-7.73 717.98,175.52 758.47,216.01 v1(761.73,216.01)
  Int1 (PWR) w7: v1(761.73,216.01) 792.55,246.83 v1(792.55,373.71)
  Int2 (GND) w7: v1(117.17,-30) 65.16,-30 33.66,-61.5 -132.83,-61.5 -178.92,-15.41 -212.16,-15.41 -254.87,27.3 -254.87,43.45 -243.45,54.88 -189.8,54.88 -181.42,46.5 -84.91,46.5 -2.38,129.04 -2.38,180.16 -7.32,185.11 -7.32,201.26 -2.38,206.21 -2.38,257.62 18,278 18,363.87 29.13,375 62.04,375 62.66,375.63 262.54,375.63 268.17,370 405,370 415.21,359.79 472.26,359.79 497.47,385 557.42,385 565.79,393.37 581.95,393.37 584.17,391.15 584.89,391.15 596.31,379.72 596.31,379 601.61,373.71 v1(792.55,373.71)
  Bottom Layer w7: v1(117.17,-30) 117.17,48.61 164.15,95.59 U2.9@164.15,102.68 ; J52.8@602.9,-96.13 v1(675.82,-96.13)
SDA: J52.7 U2.10 | length 825.2
  Top Layer w7: v1(224.76,-170.38) 267.93,-170.38 345.4,-92.91 426.22,-92.91 v1(442.2,-108.89)
  Int1 (PWR) w7: v1(20.62,-30) 9.74,-40.87 9.74,-113.23 21.38,-124.87 22.99,-124.87 50.94,-152.82 203.68,-152.82 221.24,-170.38 v1(224.76,-170.38)
  Bottom Layer w7: v1(20.62,-30) 57.93,-30 70.06,-17.87 80.33,-17.87 90,-8.2 90,41.12 144.47,95.59 U2.10@144.47,102.68 ; v1(442.2,-108.89) 442.2,-117.8 442.67,-117.33 J52.7@442.67,-96.13
SPI1_CS: U3.28 U5.15 U6.28 U8.28 U10.1 | length 3760.6
  Top Layer w7: U6.28@-655,-162.09 -654.34,-162.75 -612.58,-162.75 v1(-611.91,-163.42) ; v1(-451,554) -432.36,535.36 U8.28@-432.36,500 ; U3.28@66.34,-596.22 66.34,-632.27 79.67,-645.6 193.38,-645.6 206.48,-632.5 v1(210,-632.5) ; v1(239,-289) 242.52,-289 248.52,-295 335.49,-295 345.49,-285 U5.15@345.49,-182.1
  Int1 (PWR) w7: v1(-611.91,-163.42) -611.25,-163.42 -611.1,-163.42 -598.34,-150.66 -598.34,-105.76 -604.6,-99.5 -613.08,-99.5 -617.08,-95.5 -707.08,-95.5 -895.5,92.92 -895.5,162.08 -503.58,554 v1(-451,554) -448.51,551.51 -436.04,551.51 -414.02,529.5 -397.87,529.5 -375.85,551.51 -373.49,551.51 -325.17,599.83 -315.17,599.83 -309.56,605.44 -307.9,605.44 -296.48,616.86 -296.48,618.52 -285,630 -224.55,630 -194.55,660 -142.58,660 -133.08,650.5 -116.92,650.5 -109.42,658 -35.58,658 -2.58,625 29.43,625 42.85,638.42 v1(45,638.42) ; v1@-611.25,-164.08 -552,-223.33 -552,-360.42 -369.5,-542.92 -369.5,-543.23 -292.73,-620 42.58,-620 66.9,-644.33 194.66,-644.33 206.48,-632.5 v1(210,-632.5)
  Int2 (GND) w7: v1(210,-632.5) 224.72,-617.78 224.72,-613.28 237.74,-600.26 237.74,-408.1 239,-406.85 v1(239,-289)
  Bottom Layer w7: U10.1@2.29,595.59 36.92,595.59 45,603.67 v1(45,638.42)
SPI1_MOSI: U5.41
SPI2_CS: J52.6 U2.17 U5.25 | length 1574.5
  Top Layer w7: U5.25@573.84,-130.91 660.78,-130.91 v1(676,-146.13)
  Int2 (GND) w7: v1(53.56,277.16) 30,300.72 30,358.9 34.1,363 67.01,363 67.63,363.63 257.57,363.63 273.41,347.79 477.23,347.79 502.44,373 530.45,373 549.08,354.37 566.51,354.37 568.74,352.15 584.89,352.15 587.11,354.37 605.31,354.37 612.65,361.71 674.19,361.71 680.5,355.4 v1(680.5,186.46)
  Bottom Layer w7: v1(53.56,277.16) 53.56,225.87 58.28,221.15 59.25,221.15 70.68,209.73 70.68,209.41 73.08,207.01 U2.17@79.51,207.01 ; J52.6@602.9,-146.13 v1(676,-146.13) 676,-123.53 702.5,-97.03 702.5,-70.93 714.5,-58.93 714.5,118.08 692.99,139.59 692.99,170.46 680.5,182.95 v1(680.5,186.46)
SPI2_MISO: J52.3 U2.14 U5.27 | length 1724.3
  Top Layer w7: v1(520.46,-94) 522,-92.46 572.92,-92.46 U5.27@573.84,-91.54
  Int1 (PWR) w7: v1(0,-290) -2.25,-292.25 -102.75,-292.25 -145,-250 -145,-210 -113,-178 -70.58,-178 -23.08,-130.5 -6.92,-130.5 11.44,-148.87 13.05,-148.87 42.15,-177.96 133.72,-177.96 157.64,-201.88 243.9,-201.88 267.82,-177.96 423.3,-177.96 504.78,-96.49 517.97,-96.49 v1(520.46,-94)
  Bottom Layer w7: v1(0,-290) 0,-286.48 11.5,-274.98 11.5,-262.42 19.5,-254.42 19.5,-155.4 -20,-115.9 -20,20 5,45 5,98.03 54.92,147.95 U2.14@79.51,147.95 ; J52.3@442.67,-196.13 449.94,-188.86 503.99,-188.86 532.31,-160.54 532.31,-122.18 522.95,-112.82 522.95,-96.49 v1(520.46,-94)
SPI2_MOSI: J52.4 U2.15 U5.28 | length 1471.4
  Top Layer w7: U5.28@573.84,-71.86 623.97,-71.86 667.75,-115.63 673.08,-115.63 695.5,-138.06 695.5,-174.5 v1(680,-190)
  Int1 (PWR) w7: v1(-15,-150) -11.48,-150 -0.62,-160.87 8.08,-160.87 37.17,-189.96 128.75,-189.96 152.66,-213.88 248.87,-213.88 272.79,-189.96 428.27,-189.96 504.74,-113.5 603.5,-113.5 v1(680,-190)
  Bottom Layer w7: v1(-15,-150) -39.1,-125.9 -39.1,20.9 -10.88,49.12 -10.88,99.12 57.64,167.64 U2.15@79.51,167.64 ; J52.4@602.9,-196.13 603.8,-195.24 671.25,-195.24 676.48,-190 v1(680,-190)
SPI2_SCK: J52.5 U2.16 U5.26 | length 1197.7
  Top Layer w7: v1(0,-180.37) 2.49,-177.88 2.49,-160.36 55,-107.85 55,13.03 101.2,59.23 101.2,133.8 53.66,181.34 53.66,199.17 v1(51.18,201.65) ; v1(512.81,-133) 515.3,-130.51 524.34,-130.51 543.62,-111.23 U5.26@573.84,-111.23
  Int1 (PWR) w7: v1(0,-180.37) 0,-183.88 12.39,-196.27 12.39,-197.8 18.5,-203.92 122.14,-203.92 144.11,-225.88 253.84,-225.88 277.76,-201.96 443.85,-201.96 v1(512.81,-133)
  Bottom Layer w7: v1(51.18,201.65) 53.66,199.17 60.58,199.17 71.62,188.12 78.71,188.12 U2.16@79.51,187.32 ; J52.5@442.67,-146.14 453.73,-135.07 510.74,-135.07 v1(512.81,-133)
